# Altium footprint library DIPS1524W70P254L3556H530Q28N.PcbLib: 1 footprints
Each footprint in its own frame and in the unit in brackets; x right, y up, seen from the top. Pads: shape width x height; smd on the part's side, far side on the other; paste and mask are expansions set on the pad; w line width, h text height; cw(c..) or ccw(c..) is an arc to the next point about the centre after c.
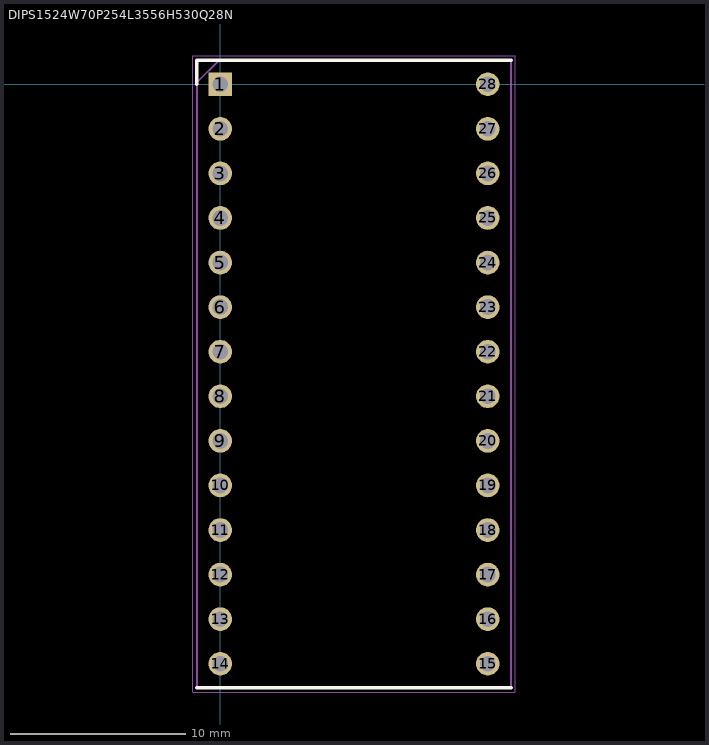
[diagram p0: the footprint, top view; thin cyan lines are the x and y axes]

## DIPS1524W70P254L3556H530Q28N [mm]
pads (28):
  rect 1.35x1.35 / inner round 1.35 / far side rect 1.35x1.35 hole 0.9: 1(0,0)
  round 1.35 hole 0.9: 2(0,-2.54) 3(0,-5.08) 4(0,-7.62) 5(0,-10.16) 6(0,-12.7) 7(0,-15.24) 8(0,-17.78) 9(0,-20.32) 10(0,-22.86) 11(0,-25.4) 12(0,-27.94) 13(0,-30.48) 14(0,-33.02) 15(15.24,-33.02) 16(15.24,-30.48) 17(15.24,-27.94) 18(15.24,-25.4) 19(15.24,-22.86) 20(15.24,-20.32) 21(15.24,-17.78) 22(15.24,-15.24) 23(15.24,-12.7) 24(15.24,-10.16) 25(15.24,-7.62) 26(15.24,-5.08) 27(15.24,-2.54) 28(15.24,0)
Top Overlay:
  lines w0.2: -1.33,-34.39 16.57,-34.39 ; -1.33,0 -1.33,1.37 16.57,1.37
Mechanical 15:
  lines w0.1: -1.33,0.1 -0.06,1.37 ; -1.33,-34.39 16.57,-34.39 16.57,1.37 -1.33,1.37 -1.33,-34.39
Mechanical 20:
  lines w0.05: -1.58,-34.64 16.82,-34.64 16.82,1.62 -1.58,1.62 -1.58,-34.64
3D body "ArduinoMetroMini v24.step": height 9.58, standoff 5.08, extent -0.903,-38.989 16.397,3.81
3D body "c-1-2199299-2-a-3d.stp": height 5.08, standoff -3.02, extent -1.23,-34.417 16.47,1.143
